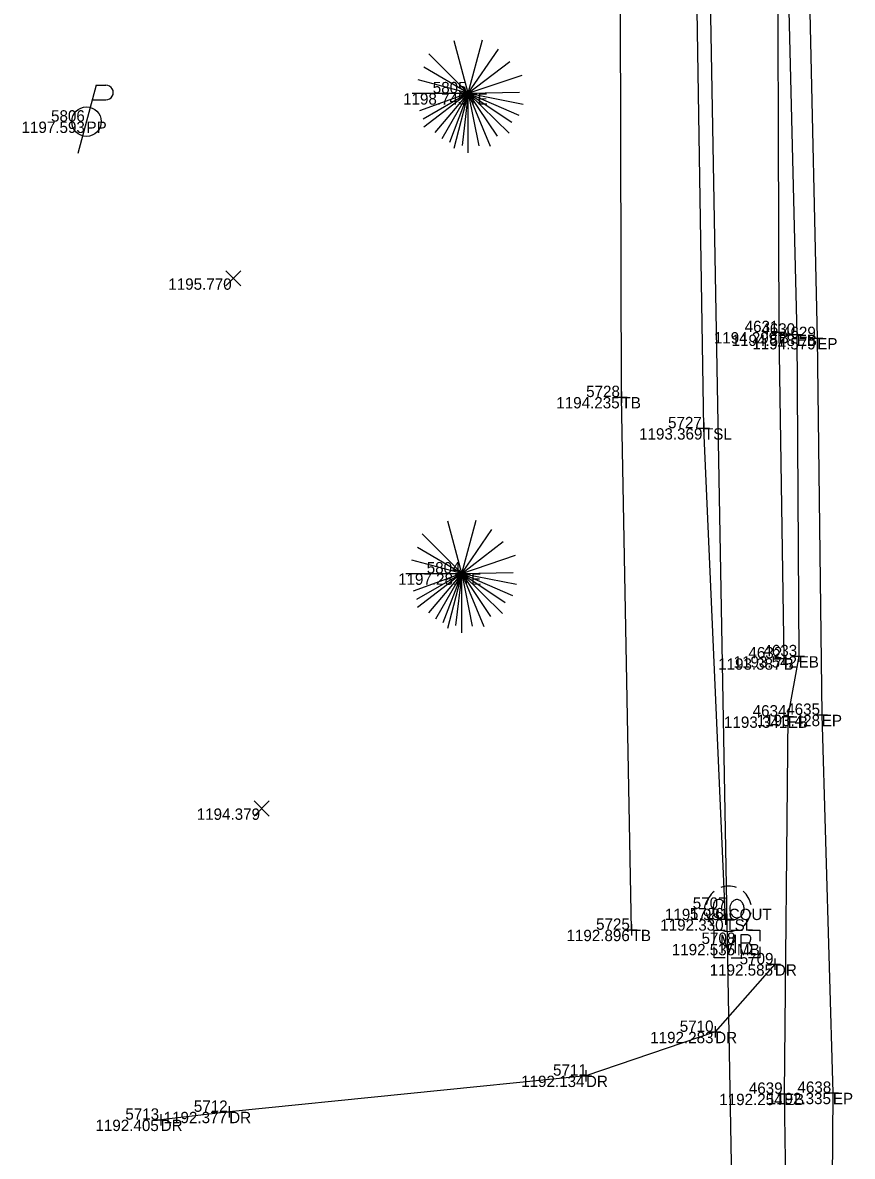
# Model space of a CAD drawing. Extents: x 2044996 to 2050343, y 455232 to 458054.
# Drawn here: x 2047565.5 to 2047638.6, y 456240.2 to 456340.1 of the extents above; entities that cross this region are included whole.
import ezdxf

# ---------------------------------------------------------------- set-up
doc = ezdxf.new("R2010")
doc.units = 0
for name, color, linetype in [('DR_X_Cells', 7, 'Continuous'), ('DR_X_Storm_Sewer', 7, 'Continuous'), ('DT_X_Contour_Minor', 7, 'Continuous'), ('DT_X_Contour_Text', 7, 'Continuous'), ('DT_X_Spot_Elev', 7, 'Continuous'), ('DT_X_Triangles', 7, 'Continuous'), ('DT_X_Void', 7, 'Continuous'), ('PV_X_Driveway', 7, 'Continuous'), ('PV_X_EOP', 7, 'Continuous'), ('PV_X_Shoulder_Aggregate', 7, 'Continuous'), ('RD_X_Cells', 7, 'Continuous'), ('SV_X_Break_Lines', 7, 'Continuous'), ('SV_X_Toe_of_Slope', 7, 'Continuous'), ('SV_X_Top_of_Bank', 7, 'Continuous'), ('UT_X_Electric_Cells', 7, 'Continuous'), ('VG_X_Cells', 7, 'Continuous')]:
    doc.layers.add(name, color=color, linetype=linetype)

msp = doc.modelspace()

# ---------------------------------------------------------------- linework, layer by layer
at = {"layer": 'DR_X_Cells'}
msp.add_line((2047627.707, 456262.034), (2047627.707, 456262.034), dxfattribs=at)
for points in [[(2047627.293, 456262.519), (2047627.23, 456262.658), (2047627.167, 456262.733), (2047627.104, 456262.784), (2047627.053, 456262.809), (2047626.915, 456262.834), (2047626.776, 456262.834), (2047626.6, 456262.784), (2047626.499, 456262.708), (2047626.449, 456262.645), (2047626.398, 456262.557), (2047626.361, 456262.418), (2047626.348, 456262.166), (2047626.348, 456261.978), (2047626.348, 456261.852), (2047626.361, 456261.738), (2047626.398, 456261.537), (2047626.411, 456261.499), (2047626.461, 456261.411), (2047626.512, 456261.348), (2047626.6, 456261.285), (2047626.675, 456261.259), (2047626.776, 456261.234), (2047626.89, 456261.234), (2047627.003, 456261.247), (2047627.041, 456261.259), (2047627.091, 456261.285), (2047627.142, 456261.335), (2047627.204, 456261.398), (2047627.255, 456261.474), (2047627.293, 456261.537)], [(2047628.313, 456262.822), (2047628.275, 456262.809), (2047628.237, 456262.796), (2047628.175, 456262.759), (2047628.137, 456262.733), (2047628.074, 456262.683), (2047628.023, 456262.633), (2047627.998, 456262.608), (2047627.96, 456262.557), (2047627.897, 456262.431), (2047627.847, 456262.305), (2047627.822, 456262.192), (2047627.809, 456262.028), (2047627.822, 456261.852), (2047627.86, 456261.726), (2047627.897, 456261.625), (2047627.923, 456261.575), (2047627.96, 456261.511), (2047628.011, 456261.449), (2047628.049, 456261.411), (2047628.086, 456261.373), (2047628.137, 456261.335), (2047628.2, 456261.297), (2047628.313, 456261.247), (2047628.376, 456261.234), (2047628.502, 456261.234), (2047628.553, 456261.247), (2047628.603, 456261.259), (2047628.666, 456261.285), (2047628.729, 456261.323), (2047628.767, 456261.348), (2047628.804, 456261.373), (2047628.842, 456261.411), (2047628.88, 456261.461), (2047628.905, 456261.499), (2047628.93, 456261.537), (2047628.956, 456261.575), (2047628.993, 456261.65), (2047629.031, 456261.738), (2047629.056, 456261.839), (2047629.069, 456261.927), (2047629.069, 456261.94), (2047629.069, 456262.028), (2047629.069, 456262.104), (2047629.056, 456262.204), (2047629.031, 456262.305), (2047629.006, 456262.381), (2047628.968, 456262.469), (2047628.93, 456262.544), (2047628.867, 456262.62), (2047628.817, 456262.67), (2047628.767, 456262.721), (2047628.716, 456262.759), (2047628.641, 456262.796), (2047628.565, 456262.822), (2047628.489, 456262.834), (2047628.401, 456262.834), (2047628.313, 456262.822)]]:
    msp.add_lwpolyline(points, dxfattribs=at)
for start, end in [(130.0806, 170.07213), (70.05767, 110.10608), (10.01689, 50.03919), (190.01689, 230.03919), (310.01144, 350.02638), (250.05767, 290.04731)]:
    msp.add_arc((2047627.706, 456262.033), 2, start, end, dxfattribs=at)
at = {"layer": 'DR_X_Storm_Sewer'}
msp.add_line((2047618.836, 456740.614), (2047628.622, 456202.215), dxfattribs=at)
at = {"layer": 'DT_X_Spot_Elev'}
for p, q in [((2047583.424, 456316.916), (2047584.757, 456318.251)), ((2047583.424, 456318.251), (2047584.757, 456316.916)), ((2047585.903, 456270.2), (2047587.236, 456271.535)), ((2047585.903, 456271.535), (2047587.236, 456270.2))]:
    msp.add_line(p, q, dxfattribs=at)
at = {"layer": 'DT_X_Void'}
for p, q in [((2047632.117, 456313.348), (2047632.117, 456312.348)), ((2047631.617, 456312.848), (2047632.617, 456312.848)), ((2047632.117, 456312.848), (2047632.117, 456312.848)), ((2047633.205, 456312.628), (2047634.205, 456312.628)), ((2047633.705, 456313.128), (2047633.705, 456312.128)), ((2047633.705, 456312.628), (2047633.705, 456312.628)), ((2047635.008, 456312.326), (2047636.008, 456312.326)), ((2047635.508, 456312.826), (2047635.508, 456311.826)), ((2047635.508, 456312.326), (2047635.508, 456312.326)), ((2047618.273, 456307.626), (2047618.273, 456306.626)), ((2047617.773, 456307.126), (2047618.773, 456307.126)), ((2047618.273, 456307.126), (2047618.273, 456307.126)), ((2047625.032, 456304.378), (2047626.032, 456304.378)), ((2047625.532, 456304.878), (2047625.532, 456303.878)), ((2047625.532, 456304.378), (2047625.532, 456304.378)), ((2047632.562, 456284.597), (2047632.562, 456283.597)), ((2047633.375, 456284.288), (2047634.375, 456284.288)), ((2047633.875, 456284.788), (2047633.875, 456283.788)), ((2047633.875, 456284.288), (2047633.875, 456284.288)), ((2047632.062, 456284.097), (2047633.062, 456284.097)), ((2047632.562, 456284.097), (2047632.562, 456284.097)), ((2047632.911, 456279.474), (2047632.911, 456278.474)), ((2047635.909, 456279.621), (2047635.909, 456278.621)), ((2047632.411, 456278.974), (2047633.411, 456278.974)), ((2047632.911, 456278.974), (2047632.911, 456278.974)), ((2047635.409, 456279.121), (2047636.409, 456279.121)), ((2047635.909, 456279.121), (2047635.909, 456279.121)), ((2047627.417, 456261.599), (2047627.417, 456260.599)), ((2047619.16, 456260.676), (2047619.16, 456259.676)), ((2047626.917, 456261.099), (2047627.917, 456261.099)), ((2047627.417, 456261.099), (2047627.417, 456261.099)), ((2047618.66, 456260.176), (2047619.66, 456260.176)), ((2047619.16, 456260.176), (2047619.16, 456260.176)), ((2047631.78, 456257.636), (2047631.78, 456256.636)), ((2047631.28, 456257.136), (2047632.28, 456257.136)), ((2047631.78, 456257.136), (2047631.78, 456257.136)), ((2047626.52, 456251.681), (2047626.52, 456250.681)), ((2047626.02, 456251.181), (2047627.02, 456251.181)), ((2047626.52, 456251.181), (2047626.52, 456251.181)), ((2047614.637, 456247.319), (2047615.637, 456247.319)), ((2047615.137, 456247.819), (2047615.137, 456246.819)), ((2047615.137, 456247.319), (2047615.137, 456247.319)), ((2047636.885, 456246.308), (2047636.885, 456245.308)), ((2047632.085, 456245.725), (2047633.085, 456245.725)), ((2047632.585, 456246.225), (2047632.585, 456245.225)), ((2047632.585, 456245.725), (2047632.585, 456245.725)), ((2047636.385, 456245.808), (2047637.385, 456245.808)), ((2047636.885, 456245.808), (2047636.885, 456245.808)), ((2047583.718, 456244.633), (2047583.718, 456243.633)), ((2047577.182, 456243.439), (2047578.182, 456243.439)), ((2047577.682, 456243.939), (2047577.682, 456242.939)), ((2047577.682, 456243.439), (2047577.682, 456243.439)), ((2047583.218, 456244.133), (2047584.218, 456244.133)), ((2047583.718, 456244.133), (2047583.718, 456244.133))]:
    msp.add_line(p, q, dxfattribs=at)
at = {"layer": 'PV_X_Driveway'}
msp.add_lwpolyline([(2047631.78, 456257.136), (2047626.52, 456251.181), (2047615.137, 456247.319), (2047583.718, 456244.133), (2047577.682, 456243.439)], dxfattribs=at)
at = {"layer": 'PV_X_EOP'}
for p, q in [((2047634.49, 456356.936), (2047635.508, 456312.326)), ((2047635.508, 456312.326), (2047635.909, 456279.121)), ((2047635.909, 456279.121), (2047636.885, 456245.808)), ((2047636.885, 456245.808), (2047636.754, 456224.871))]:
    msp.add_line(p, q, dxfattribs=at)
at = {"layer": 'PV_X_Shoulder_Aggregate'}
for p, q in [((2047632.617, 456356.871), (2047633.705, 456312.628)), ((2047633.705, 456312.628), (2047633.875, 456284.288)), ((2047633.875, 456284.288), (2047632.911, 456278.974)), ((2047632.911, 456278.974), (2047632.585, 456245.725)), ((2047632.585, 456245.725), (2047632.77, 456233.472))]:
    msp.add_line(p, q, dxfattribs=at)
at = {"layer": 'RD_X_Cells'}
for p, q in [((2047627.93, 456260.151), (2047628.931, 456260.151)), ((2047628.441, 456258.929), (2047628.441, 456258.929)), ((2047627.93, 456257.707), (2047628.931, 456257.707))]:
    msp.add_line(p, q, dxfattribs=at)
for points in [[(2047626.441, 456259.181), (2047626.441, 456260.151), (2047627.411, 456260.151)], [(2047627.145, 456258.129), (2047627.145, 456259.729), (2047627.724, 456258.129), (2047628.279, 456259.729), (2047628.279, 456258.129)], [(2047629.463, 456258.998), (2047629.526, 456259.061), (2047629.564, 456259.099), (2047629.589, 456259.137), (2047629.601, 456259.162), (2047629.627, 456259.212), (2047629.639, 456259.25), (2047629.665, 456259.338), (2047629.665, 456259.376), (2047629.665, 456259.427), (2047629.652, 456259.502), (2047629.627, 456259.565), (2047629.589, 456259.615), (2047629.526, 456259.666), (2047629.475, 456259.691), (2047629.45, 456259.704), (2047629.387, 456259.729), (2047628.77, 456259.729), (2047628.77, 456258.129), (2047629.463, 456258.129), (2047629.551, 456258.179), (2047629.627, 456258.242), (2047629.69, 456258.343), (2047629.727, 456258.456), (2047629.74, 456258.57), (2047629.74, 456258.646), (2047629.715, 456258.721), (2047629.665, 456258.834), (2047629.601, 456258.91), (2047629.463, 456258.998), (2047628.77, 456258.998)], [(2047629.448, 456260.151), (2047630.441, 456260.151), (2047630.441, 456259.181)], [(2047627.411, 456257.707), (2047626.441, 456257.707), (2047626.441, 456258.677)], [(2047630.441, 456258.677), (2047630.441, 456257.707), (2047629.448, 456257.707)]]:
    msp.add_lwpolyline(points, dxfattribs=at)
at = {"layer": 'SV_X_Break_Lines'}
msp.add_lwpolyline([(2047625.208, 456638.946), (2047627.108, 456588.813), (2047628.315, 456540.514), (2047628.577, 456493.595), (2047629.456, 456445.222), (2047630.658, 456399.517), (2047631.974, 456357.069), (2047632.117, 456312.848), (2047632.562, 456284.097)], dxfattribs=at)
at = {"layer": 'SV_X_Toe_of_Slope'}
msp.add_lwpolyline([(2047627.417, 456261.099), (2047625.532, 456304.378), (2047624.707, 456355.976), (2047623.948, 456397.688), (2047623.345, 456452.183), (2047621.682, 456495.646), (2047623.554, 456542.587), (2047620.932, 456580.314), (2047618.38, 456635.969)], dxfattribs=at)
at = {"layer": 'SV_X_Top_of_Bank'}
msp.add_lwpolyline([(2047619.16, 456260.176), (2047618.273, 456307.126), (2047618.14, 456352.845), (2047617.013, 456400.111), (2047615.659, 456448.081), (2047612.43, 456496.095), (2047612.663, 456543.64), (2047611.434, 456577.895), (2047611.456, 456637.593)], dxfattribs=at)
at = {"layer": 'UT_X_Electric_Cells'}
for p, q in [((2047572.007, 456334.602), (2047570.4, 456328.602)), ((2047572.007, 456334.602), (2047572.857, 456334.602)), ((2047571.665, 456333.327), (2047572.857, 456333.327))]:
    msp.add_line(p, q, dxfattribs=at)
msp.add_circle((2047571.15, 456331.402), 1.3, dxfattribs=at)
msp.add_arc((2047572.869, 456333.964), 0.638, 268.8767, 91.1233, dxfattribs=at)
at = {"layer": 'VG_X_Cells'}
for p, q in [((2047604.776, 456333.898), (2047603.541, 456338.511)), ((2047604.776, 456333.898), (2047606.032, 456338.596)), ((2047604.776, 456333.898), (2047601.286, 456337.385)), ((2047604.776, 456333.898), (2047607.431, 456337.783)), ((2047604.776, 456333.898), (2047608.432, 456336.703)), ((2047604.776, 456333.898), (2047600.869, 456336.195)), ((2047604.776, 456333.898), (2047609.512, 456335.505)), ((2047604.776, 456333.898), (2047600.362, 456335.081)), ((2047599.841, 456333.898), (2047604.776, 456333.898)), ((2047604.776, 456333.898), (2047600.486, 456332.336)), ((2047604.776, 456333.898), (2047600.792, 456331.616)), ((2047604.776, 456333.898), (2047600.869, 456330.903)), ((2047604.776, 456333.898), (2047601.831, 456330.431)), ((2047604.776, 456333.898), (2047602.457, 456329.883)), ((2047604.776, 456333.898), (2047603.111, 456329.558)), ((2047604.776, 456333.898), (2047603.512, 456329.041)), ((2047604.776, 456333.898), (2047604.234, 456329.306)), ((2047604.776, 456333.898), (2047609.286, 456333.99)), ((2047604.776, 456328.658), (2047604.776, 456333.898)), ((2047604.776, 456333.898), (2047605.697, 456329.261)), ((2047604.776, 456333.898), (2047606.709, 456329.23)), ((2047604.776, 456333.898), (2047607.312, 456330.105)), ((2047604.776, 456333.898), (2047608.364, 456330.376)), ((2047604.776, 456333.898), (2047608.597, 456331.343)), ((2047604.776, 456333.898), (2047609.241, 456331.956)), ((2047604.776, 456333.898), (2047609.604, 456332.94)), ((2047604.205, 456291.579), (2047605.461, 456296.278)), ((2047604.205, 456291.579), (2047602.97, 456296.193)), ((2047604.205, 456291.579), (2047606.86, 456295.464)), ((2047604.205, 456291.579), (2047600.715, 456295.066)), ((2047604.205, 456291.579), (2047607.861, 456294.384)), ((2047604.205, 456291.579), (2047600.298, 456293.876)), ((2047604.205, 456291.579), (2047599.791, 456292.763)), ((2047604.205, 456291.579), (2047608.941, 456293.186)), ((2047599.27, 456291.579), (2047604.205, 456291.579)), ((2047604.205, 456291.579), (2047599.915, 456290.018)), ((2047604.205, 456291.579), (2047600.221, 456289.298)), ((2047604.205, 456291.579), (2047600.298, 456288.584)), ((2047604.205, 456291.579), (2047601.26, 456288.113)), ((2047604.205, 456291.579), (2047601.886, 456287.564)), ((2047604.205, 456291.579), (2047602.54, 456287.239)), ((2047604.205, 456291.579), (2047602.941, 456286.723)), ((2047604.205, 456291.579), (2047603.663, 456286.988)), ((2047604.205, 456291.579), (2047608.715, 456291.671)), ((2047604.205, 456286.339), (2047604.205, 456291.579)), ((2047604.205, 456291.579), (2047605.126, 456286.943)), ((2047604.205, 456291.579), (2047606.138, 456286.911)), ((2047604.205, 456291.579), (2047606.741, 456287.786)), ((2047604.205, 456291.579), (2047607.793, 456288.058)), ((2047604.205, 456291.579), (2047608.026, 456289.024)), ((2047604.205, 456291.579), (2047608.67, 456289.638)), ((2047604.205, 456291.579), (2047609.033, 456290.621))]:
    msp.add_line(p, q, dxfattribs=at)

# ---------------------------------------------------------------- texts
at = {"layer": 'DT_X_Contour_Minor'}
for s, p in [('1198.745', (2047599.032, 456332.898)), ('1197.593', (2047565.427, 456330.402)), ('1195.770', (2047578.356, 456316.583)), ('1194.299', (2047626.402, 456311.848)), ('1194.578', (2047627.972, 456311.628)), ('1194.579', (2047629.794, 456311.326)), ('1194.235', (2047612.529, 456306.126)), ('1193.369', (2047619.818, 456303.378)), ('1197.281', (2047598.591, 456290.579)), ('1193.542', (2047628.145, 456283.288)), ('1193.387', (2047626.786, 456283.097)), ('1193.341', (2047627.297, 456277.974)), ('1193.428', (2047630.177, 456278.121)), ('1194.379', (2047580.855, 456269.867)), ('1191.981', (2047622.094, 456261.034)), ('1192.330', (2047621.683, 456260.099)), ('1192.896', (2047613.423, 456259.176)), ('1192.535', (2047622.697, 456257.929)), ('1192.585', (2047626.036, 456256.136)), ('1192.283', (2047620.797, 456250.181)), ('1192.134', (2047609.432, 456246.319)), ('1192.254', (2047626.88, 456244.725)), ('1192.335', (2047631.141, 456244.808)), ('1192.405', (2047571.938, 456242.439)), ('1192.377', (2047577.942, 456243.133))]:
    msp.add_text(s, height=1, dxfattribs=at).set_placement(p)
at = {"layer": 'DT_X_Contour_Text'}
for s, p in [('TE', (2047604.776, 456332.898)), ('PP', (2047571.15, 456330.402)), ('B', (2047632.117, 456311.848)), ('EB', (2047633.705, 456311.628)), ('EP', (2047635.508, 456311.326)), ('TB', (2047618.273, 456306.126)), ('TSL', (2047625.532, 456303.378)), ('TE', (2047604.205, 456290.579)), ('EB', (2047633.875, 456283.288)), ('B', (2047632.562, 456283.097)), ('EB', (2047632.911, 456277.974)), ('EP', (2047635.909, 456278.121)), ('COUT', (2047627.707, 456261.034)), ('TSL', (2047627.417, 456260.099)), ('TB', (2047619.16, 456259.176)), ('MB', (2047628.441, 456257.929)), ('DR', (2047631.78, 456256.136)), ('DR', (2047626.52, 456250.181)), ('DR', (2047615.137, 456246.319)), ('EB', (2047632.585, 456244.725)), ('EP', (2047636.885, 456244.808)), ('DR', (2047577.682, 456242.439)), ('DR', (2047583.718, 456243.133))]:
    msp.add_text(s, height=1, dxfattribs=at).set_placement(p)
at = {"layer": 'DT_X_Triangles'}
for s, p in [('5805', (2047601.646, 456333.898)), ('5806', (2047568.027, 456331.402)), ('4631', (2047629.117, 456312.848)), ('4630', (2047630.585, 456312.628)), ('4629', (2047632.408, 456312.326)), ('5728', (2047615.155, 456307.126)), ('5727', (2047622.37, 456304.378)), ('5804', (2047601.115, 456291.579)), ('4633', (2047630.767, 456284.288)), ('4632', (2047629.447, 456284.097)), ('4634', (2047629.821, 456278.974)), ('4635', (2047632.779, 456279.121)), ('5707', (2047624.546, 456262.034)), ('5726', (2047624.294, 456261.099)), ('5725', (2047616.031, 456260.176)), ('5708', (2047625.323, 456258.929)), ('5709', (2047628.68, 456257.136)), ('5710', (2047623.4, 456251.181)), ('5711', (2047612.241, 456247.319)), ('4639', (2047629.485, 456245.725)), ('4638', (2047633.767, 456245.808)), ('5713', (2047574.573, 456243.439)), ('5712', (2047580.603, 456244.133))]:
    msp.add_text(s, height=1, dxfattribs=at).set_placement(p)

doc.saveas('drawing.dxf')
